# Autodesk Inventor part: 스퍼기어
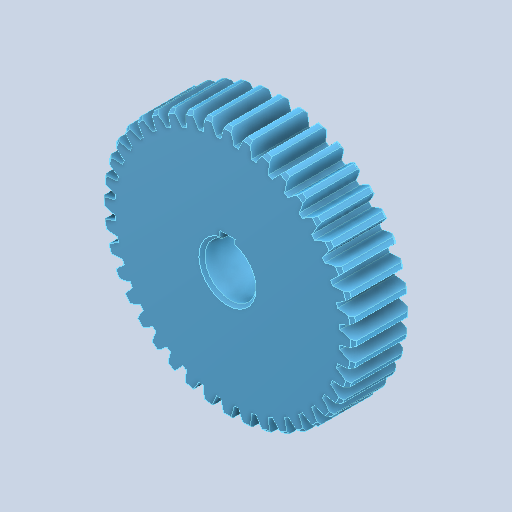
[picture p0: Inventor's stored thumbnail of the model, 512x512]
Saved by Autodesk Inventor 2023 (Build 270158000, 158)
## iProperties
Created: 2025-03
Part Number: 스퍼기어
Material: 알루미늄 6061
Document SubType Name: Modeling
Designer: User
Density: 2.71 g/cm^3
Appearance: 기본값
Author: jhkim
Sending System: Autodesk Inventor 2025
Preprocessor: ST-DEVELOPER v20
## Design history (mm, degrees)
feature "Solid1"
node "솔리드1"
